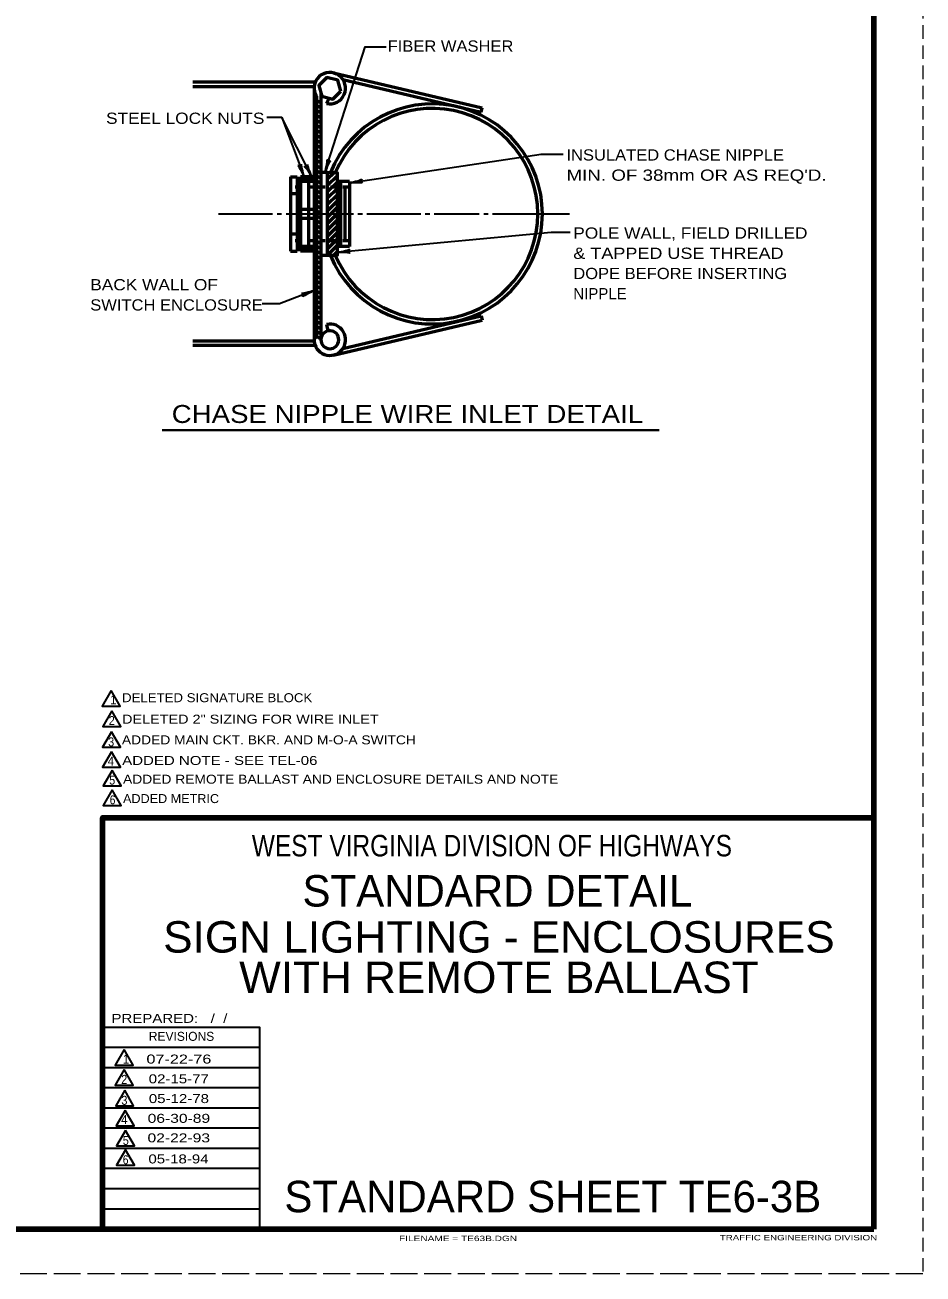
# Model space of a CAD drawing. Extents: x -77 to 603, y -47 to 393.
# Drawn here: x 403.1 to 603.1, y -46.8 to 231.3 of the extents above; entities that cross this region are included whole.
import ezdxf
from ezdxf.enums import TextEntityAlignment as Align

# ---------------------------------------------------------------- set-up
doc = ezdxf.new("R2010")
doc.units = 0
for name, pattern in [('LONG_DASHED', [7.5, 6, -1.5]), ('MEDIUM_DASHED', [4.5, 3, -1.5]), ('SHORT_DASHED', [2.7, 1.5, -1.2])]:
    doc.linetypes.add(name, pattern=pattern)
doc.layers.add('1', color=7, linetype='Continuous', lineweight=53)
doc.layers.add('61', color=7, linetype='Continuous', lineweight=35)

msp = doc.modelspace()

# ---------------------------------------------------------------- linework, layer by layer
at = {"layer": '1', "linetype": 'MEDIUM_DASHED', "lineweight": 13}
msp.add_line((603.055, 393.264), (603.035, -46.756), dxfattribs=at)
at = {"layer": '1'}
for p, q in [((471.839, 220.696), (504.888, 212.859)), ((467.758, 218.556), (440.517, 218.556)), ((467.517, 217.556), (440.517, 217.556)), ((467.502, 217.242), (467.502, 161.242)), ((473.92, 219.174), (504.657, 211.886)), ((467.502, 214.026), (468.002, 214.526)), ((468.002, 215.439), (468.002, 161.977)), ((468.002, 214.526), (469.002, 214.026)), ((469.002, 216.349), (469.002, 161.242)), ((470.283, 213.816), (470.892, 215.033)), ((467.502, 212.93), (468.002, 213.43)), ((467.502, 211.79), (468.002, 212.29)), ((468.002, 213.408), (469.002, 212.908)), ((468.002, 212.29), (469.002, 211.79)), ((504.657, 211.886), (504.888, 212.859)), ((467.502, 210.672), (468.002, 211.172)), ((467.502, 209.554), (468.002, 210.054)), ((467.502, 208.436), (468.002, 208.936)), ((468.002, 211.172), (469.002, 210.672)), ((468.002, 210.054), (469.002, 209.554)), ((468.002, 208.936), (469.002, 208.436)), ((467.502, 207.318), (468.002, 207.818)), ((467.502, 206.2), (468.002, 206.7)), ((468.002, 207.818), (469.002, 207.318)), ((468.002, 206.7), (469.002, 206.2)), ((467.502, 205.082), (468.002, 205.582)), ((467.502, 203.964), (468.002, 204.464)), ((467.502, 202.846), (468.002, 203.346)), ((468.002, 205.582), (469.002, 205.082)), ((468.002, 204.464), (469.002, 203.964)), ((468.002, 203.346), (469.002, 202.845)), ((467.502, 201.727), (468.002, 202.227)), ((467.502, 200.609), (468.002, 201.109)), ((468.002, 202.227), (469.002, 201.727)), ((468.002, 201.109), (469.002, 200.609)), ((462.252, 197.492), (462.252, 180.992)), ((462.252, 197.492), (463.752, 197.492)), ((463.752, 197.492), (463.752, 180.992)), ((467.502, 197.492), (464.502, 197.492)), ((464.502, 197.492), (464.502, 180.992)), ((466.252, 197.492), (466.252, 180.992)), ((467.502, 199.491), (468.002, 199.991)), ((467.502, 198.373), (468.002, 198.873)), ((467.502, 197.255), (468.002, 197.755)), ((468.002, 199.991), (469.002, 199.491)), ((468.002, 198.873), (469.002, 198.373)), ((468.002, 197.755), (469.002, 197.255)), ((470.502, 198.492), (469.002, 198.492)), ((470.502, 198.458), (470.536, 198.492)), ((470.502, 197.044), (471.95, 198.492)), ((470.502, 195.63), (472.627, 197.755)), ((467.502, 196.492), (463.752, 196.492)), ((467.502, 196.992), (464.502, 196.992)), ((467.502, 196.137), (468.002, 196.637)), ((467.502, 195.019), (468.002, 195.519)), ((468.002, 196.637), (469.002, 196.137)), ((468.002, 195.519), (469.002, 195.019)), ((470.502, 194.215), (472.627, 196.34)), ((470.502, 192.801), (472.627, 194.926)), ((475.377, 196.492), (472.627, 196.492)), ((473.377, 196.492), (473.377, 181.992)), ((474.377, 195.242), (474.377, 183.242)), ((475.377, 196.492), (475.377, 181.992)), ((463.752, 193.742), (462.252, 193.742)), ((467.502, 193.901), (468.002, 194.401)), ((467.502, 192.783), (468.002, 193.283)), ((467.502, 191.665), (468.002, 192.165)), ((468.002, 194.401), (469.002, 193.901)), ((468.002, 193.283), (469.002, 192.783)), ((468.002, 192.165), (469.002, 191.665)), ((470.502, 191.387), (472.627, 193.512)), ((470.502, 189.973), (472.627, 192.098)), ((467.502, 190.242), (464.502, 190.242)), ((467.502, 190.547), (468.002, 191.047)), ((467.502, 189.428), (468.002, 189.928)), ((468.002, 191.047), (469.002, 190.546)), ((468.002, 189.928), (469.002, 189.428)), ((470.502, 188.558), (472.627, 190.683)), ((470.502, 187.144), (472.627, 189.269)), ((467.502, 188.242), (464.502, 188.242)), ((467.502, 188.31), (468.002, 188.81)), ((467.502, 187.192), (468.002, 187.692)), ((467.502, 186.074), (468.002, 186.574)), ((468.002, 188.81), (469.002, 188.31)), ((468.002, 187.692), (469.002, 187.192)), ((468.002, 186.574), (469.002, 186.074)), ((470.502, 185.73), (472.627, 187.855)), ((470.502, 184.316), (472.627, 186.441)), ((463.752, 184.742), (462.252, 184.742)), ((467.502, 184.956), (468.002, 185.456)), ((467.502, 183.838), (468.002, 184.338)), ((468.002, 185.456), (469.002, 184.956)), ((468.002, 184.338), (469.002, 183.838)), ((470.502, 182.901), (472.627, 185.026)), ((470.502, 181.487), (472.627, 183.612)), ((462.252, 180.992), (463.752, 180.992)), ((467.502, 181.992), (463.752, 181.992)), ((467.502, 181.492), (464.502, 181.492)), ((467.502, 180.992), (464.502, 180.992)), ((467.502, 182.72), (468.002, 183.22)), ((467.502, 181.602), (468.002, 182.102)), ((467.502, 180.484), (468.002, 180.984)), ((468.002, 183.22), (469.002, 182.72)), ((468.002, 182.102), (469.002, 181.602)), ((468.002, 180.984), (469.002, 180.484)), ((470.502, 180.073), (472.627, 182.198)), ((471.835, 179.992), (472.627, 180.784)), ((475.377, 181.992), (472.627, 181.992)), ((467.502, 179.366), (468.002, 179.866)), ((467.502, 178.248), (468.002, 178.748)), ((468.002, 179.866), (469.002, 179.366)), ((468.002, 178.748), (469.002, 178.248)), ((470.502, 179.992), (469.002, 179.992)), ((467.502, 177.13), (468.002, 177.63)), ((467.502, 176.012), (468.002, 176.512)), ((467.502, 174.893), (468.002, 175.393)), ((468.002, 177.63), (469.002, 177.13)), ((468.002, 176.512), (469.002, 176.011)), ((468.002, 175.393), (469.002, 174.893)), ((467.502, 173.775), (468.002, 174.275)), ((467.502, 172.657), (468.002, 173.157)), ((468.002, 174.275), (469.002, 173.775)), ((468.002, 173.157), (469.002, 172.657)), ((467.502, 171.539), (468.002, 172.039)), ((467.502, 170.421), (468.002, 170.921)), ((467.502, 169.303), (468.002, 169.803)), ((468.002, 172.039), (469.002, 171.539)), ((468.002, 170.921), (469.002, 170.421)), ((468.002, 169.803), (469.002, 169.303)), ((467.502, 168.185), (468.002, 168.685)), ((467.502, 167.067), (468.002, 167.567)), ((468.002, 168.685), (469.002, 168.185)), ((468.002, 167.567), (469.002, 167.067)), ((467.502, 165.949), (468.002, 166.449)), ((467.502, 164.831), (468.002, 165.331)), ((467.502, 163.713), (468.002, 164.213)), ((468.002, 166.449), (469.002, 165.949)), ((468.002, 165.331), (469.002, 164.831)), ((468.002, 164.213), (469.002, 163.713)), ((470.283, 164.667), (470.591, 163.197)), ((471.839, 157.788), (504.888, 165.624)), ((473.92, 159.309), (504.657, 166.597)), ((504.657, 166.597), (504.888, 165.624)), ((467.502, 162.595), (468.002, 163.095)), ((467.502, 161.477), (468.002, 161.977)), ((468.002, 163.095), (469.002, 162.595)), ((468.002, 161.977), (469.002, 161.476)), ((467.517, 160.927), (440.517, 160.927)), ((467.758, 159.927), (440.517, 159.927))]:
    msp.add_line(p, q, dxfattribs=at)
at = {"layer": '1', "lineweight": 35}
for p, q in [((460.33, 210.688), (456.984, 210.688)), ((446.252, 189.242), (458.252, 189.242)), ((459.252, 189.242), (460.252, 189.242)), ((461.252, 189.242), (476.252, 189.242)), ((477.252, 189.242), (478.252, 189.242)), ((479.252, 189.242), (491.252, 189.242)), ((492.252, 189.242), (493.252, 189.242)), ((494.252, 189.242), (504.252, 189.242)), ((505.252, 189.242), (506.252, 189.242)), ((507.252, 189.242), (524.325, 189.242)), ((455.435, 3.664), (420.455, 3.664)), ((455.435, -0.836), (420.455, -0.836)), ((455.435, -5.336), (420.455, -5.336)), ((455.435, -9.856), (420.455, -9.856)), ((455.435, -14.336), (420.455, -14.336)), ((455.435, -18.816), (420.455, -18.816)), ((455.435, -23.316), (420.455, -23.316)), ((455.435, -27.816), (420.455, -27.816)), ((455.435, -32.336), (420.455, -32.336))]:
    msp.add_line(p, q, dxfattribs=at)
at = {"layer": '1', "linetype": 'SHORT_DASHED'}
for p, q in [((467.502, 195.242), (462.252, 195.242)), ((475.377, 195.242), (469.002, 195.242)), ((467.502, 183.242), (462.252, 183.242)), ((475.377, 183.242), (469.002, 183.242))]:
    msp.add_line(p, q, dxfattribs=at)
at = {"layer": '1', "lineweight": 40}
msp.add_line((433.674, 141.075), (544.289, 141.075), dxfattribs=at)
at = {"layer": '1', "lineweight": 35}
for points in [[(469.893, 198.492), (478.882, 226.487), (483.579, 226.487)], [(466.977, 197.492), (460.33, 210.688), (465.281, 197.492)], [(475.377, 196.147), (518.067, 202.582), (522.979, 202.582)], [(472.627, 180.701), (520.289, 185.153), (524.499, 185.153)], [(467.502, 172.204), (459.78, 169.197), (455.931, 169.197)], [(455.435, -36.816), (455.435, 8.144), (420.455, 8.144)]]:
    msp.add_lwpolyline(points, dxfattribs=at)
at = {"layer": '1'}
for points in [[(473.421, 216.61), (472.759, 219.021), (470.34, 219.652), (468.583, 217.873), (469.246, 215.463), (471.665, 214.831)], [(470.502, 179.992), (470.502, 198.492), (472.627, 198.492), (472.627, 179.992)]]:
    msp.add_lwpolyline(points, close=True, dxfattribs=at)
at = {"layer": '1', "lineweight": 35}
for points in [[(422.344, 83.13), (420.344, 79.665), (424.344, 79.665)], [(422.463, 78.615), (420.463, 75.151), (424.463, 75.151)], [(422.399, 73.966), (420.399, 70.502), (424.399, 70.502)], [(422.387, 69.521), (420.387, 66.057), (424.387, 66.057)], [(422.577, 65.347), (420.577, 61.883), (424.577, 61.883)], [(422.577, 61.032), (420.577, 57.568), (424.577, 57.568)], [(425.21, 3.202), (423.21, -0.262), (427.21, -0.262)], [(425.252, -1.243), (423.252, -4.707), (427.252, -4.707)], [(425.336, -5.86), (423.336, -9.324), (427.336, -9.324)], [(425.464, -10.348), (423.464, -13.813), (427.464, -13.813)], [(425.515, -14.801), (423.515, -18.265), (427.515, -18.265)], [(425.515, -19.108), (423.515, -22.572), (427.515, -22.572)]]:
    msp.add_lwpolyline(points, close=True, dxfattribs=at)
at = {"layer": '1', "lineweight": 158}
msp.add_lwpolyline([(420.435, -36.776), (420.435, 54.804), (592.095, 54.804)], dxfattribs=at)
at = {"layer": '1'}
for centre, radius, start, end in [((471.002, 217.242), 3.5, 258.13571, 210.93646), ((493.825, 189.242), 24.5, 202.18207, 157.81793), ((493.825, 189.242), 23.5, 203.17975, 156.82025), ((471.002, 161.242), 3.5, 180, 101.86429), ((471.002, 161.242), 1.998, 180, 176.5775)]:
    msp.add_arc(centre, radius, start, end, dxfattribs=at)
at = {"layer": '1', "lineweight": 40}
for centre, major_axis, ratio, start_param, end_param in [((465.086, 198.615), (0.453, -1.706), 0.07063, 3.1407148, 5.41811), ((465.086, 198.615), (0.453, -1.706), 0.07063, 3.1407148, 5.41811), ((466.662, 198.588), (0.633, -1.648), 0.07063, 3.1407148, 5.41811), ((469.964, 199.615), (-0.397, -1.748), 0.122415, 0.8963533, 3.1415927), ((470.437, 199.494), (0.704, 1.619), 0.07063, 6.2823074, 8.5597026), ((464.639, 198.416), (0.773, -1.617), 0.122415, 0.8963533, 3.1415927), ((464.639, 198.416), (0.773, -1.617), 0.122415, 0.8963533, 3.1415927), ((466.24, 198.342), (0.943, -1.525), 0.122415, 0.8963533, 3.1415927), ((476.415, 196.583), (-1.742, -0.421), 0.122415, 0.8963533, 3.1415927), ((476.415, 196.583), (-1.742, -0.421), 0.122415, 0.8963533, 3.1415927), ((476.517, 196.105), (1.763, 0.088), 0.07063, 6.2823074, 8.5597026), ((476.517, 196.105), (1.763, 0.088), 0.07063, 6.2823074, 8.5597026), ((473.688, 181.078), (-1.763, -0.322), 0.122415, 0.8963533, 3.1415927), ((473.688, 181.078), (-1.763, -0.322), 0.122415, 0.8963533, 3.1415927), ((473.763, 180.595), (1.765, -0.012), 0.07063, 6.2823074, 8.5597026), ((473.763, 180.595), (1.765, -0.012), 0.07063, 6.2823074, 8.5597026), ((466.381, 171.995), (1.7, 0.474), 0.07063, 3.1407148, 5.41811), ((466.586, 171.551), (1.607, 0.794), 0.122415, 0.8963533, 3.1415927)]:
    msp.add_ellipse(centre, major_axis=major_axis, ratio=ratio, start_param=start_param, end_param=end_param, dxfattribs=at)
at = {"layer": '61', "lineweight": 158}
for p, q in [((592.075, 383.264), (592.095, -36.776)), ((592.095, -36.776), (-46.965, -36.756))]:
    msp.add_line(p, q, dxfattribs=at)
at = {"layer": '61', "linetype": 'LONG_DASHED', "lineweight": 13}
msp.add_line((603.035, -46.756), (-77.025, -46.776), dxfattribs=at)

# ---------------------------------------------------------------- texts
at = {"layer": '1'}
for s, height, width, p in [('FIBER WASHER', 2.5, 1.1, (497.876, 225.373)), ('STEEL LOCK NUTS', 2.5, 1.15, (438.817, 209.302)), ('CHASE NIPPLE WIRE INLET DETAIL', 4, 1.15, (488.276, 142.707)), ('6', 2, 0.85, (422.64, 57.797)), ('WEST VIRGINIA DIVISION OF HIGHWAYS', 4.795, 0.85, (507.083, 46.204)), ('SIGN LIGHTING - ENCLOSURES', 6.993, 1.05, (508.647, 24.785)), ('WITH REMOTE BALLAST', 6.993, 1.05, (508.647, 15.792)), ('07-22-76', 2, 1.35, (437.404, 0.084)), ('02-15-77', 2, 1.25, (437.384, -4.316)), ('05-12-78', 2, 1.25, (437.404, -8.716)), ('06-30-89', 2, 1.3, (437.404, -13.116)), ('02-22-93', 2, 1.3, (437.379, -17.463)), ('05-18-94', 2, 1.25, (437.315, -22.15))]:
    msp.add_text(s, height=height, dxfattribs=dict(at, width=width)).set_placement(p, align=Align.CENTER)
for s, height, width, p in [('INSULATED CHASE NIPPLE', 2.5, 1.1, (523.68, 201.135)), ("MIN. OF 38mm OR AS REQ'D.", 2.5, 1.25, (523.68, 196.635)), ('POLE WALL, FIELD DRILLED', 2.5, 1.15, (525.201, 183.743)), ('& TAPPED USE THREAD', 2.5, 1.2, (525.201, 179.243)), ('DOPE BEFORE INSERTING', 2.5, 1.1, (525.201, 174.743)), ('BACK WALL OF', 2.5, 1.15, (417.673, 172.239)), ('SWITCH ENCLOSURE', 2.5, 1.1, (417.673, 167.739)), ('DELETED SIGNATURE BLOCK', 2, 1.1, (424.75, 80.538)), ('2', 2, 0.9, (421.791, 75.445)), ('DELETED 2" SIZING FOR WIRE INLET', 2, 1.2, (424.75, 75.764)), ('3', 2, 0.9, (421.664, 70.703)), ('ADDED MAIN CKT. BKR. AND M-O-A SWITCH', 2, 1.15, (424.719, 71.149)), ('4', 2, 0.95, (421.569, 66.438)), ('ADDED NOTE - SEE TEL-06', 2, 1.25, (424.782, 66.565)), ('5', 2, 0.9, (421.886, 62.2)), ('ADDED REMOTE BALLAST AND ENCLOSURE DETAILS AND NOTE', 2, 1.15, (424.972, 62.391)), ('ADDED METRIC', 2, 1.05, (424.972, 58.077)), ('PREPARED:   /  /  ', 1.998, 1.25, (422.395, 9.144)), ('2', 2, 0.9, (424.557, -4.447)), ('3', 2, 0.9, (424.6, -9.102)), ('4', 2, 0.95, (424.557, -13.369)), ('5', 2, 0.9, (424.911, -18.024)), ('6', 2, 0.85, (424.911, -22.331)), ('FILENAME = TE63B.DGN', 1.2, 1.4, (486.414, -39.447)), ('TRAFFIC ENGINEERING DIVISION', 1.2, 1.35, (557.815, -39.276))]:
    msp.add_text(s, height=height, dxfattribs=dict(at, width=width)).set_placement(p)
for s, height, p in [('NIPPLE', 2.5, (525.201, 170.243)), ('1', 2, (422.078, 80.06)), ('REVISIONS', 1.998, (430.715, 5.144)), ('1', 2, (424.901, 0.079))]:
    msp.add_text(s, height=height, dxfattribs=at).set_placement(p)
for s, p in [('STANDARD DETAIL', (508.305, 35.044)), ('STANDARD SHEET TE6-3B', (520.645, -33.016))]:
    msp.add_text(s, height=6.993, dxfattribs=at).set_placement(p, align=Align.CENTER)

doc.saveas('drawing.dxf')
